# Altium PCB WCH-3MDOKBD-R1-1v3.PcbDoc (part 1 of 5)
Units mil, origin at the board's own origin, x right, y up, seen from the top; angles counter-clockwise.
Board outline 11710.74 x 4477.49 mil, 2 copper layers (Top Layer, Bottom Layer); 422 components, 246 nets, 927 pads, 1295 vias.
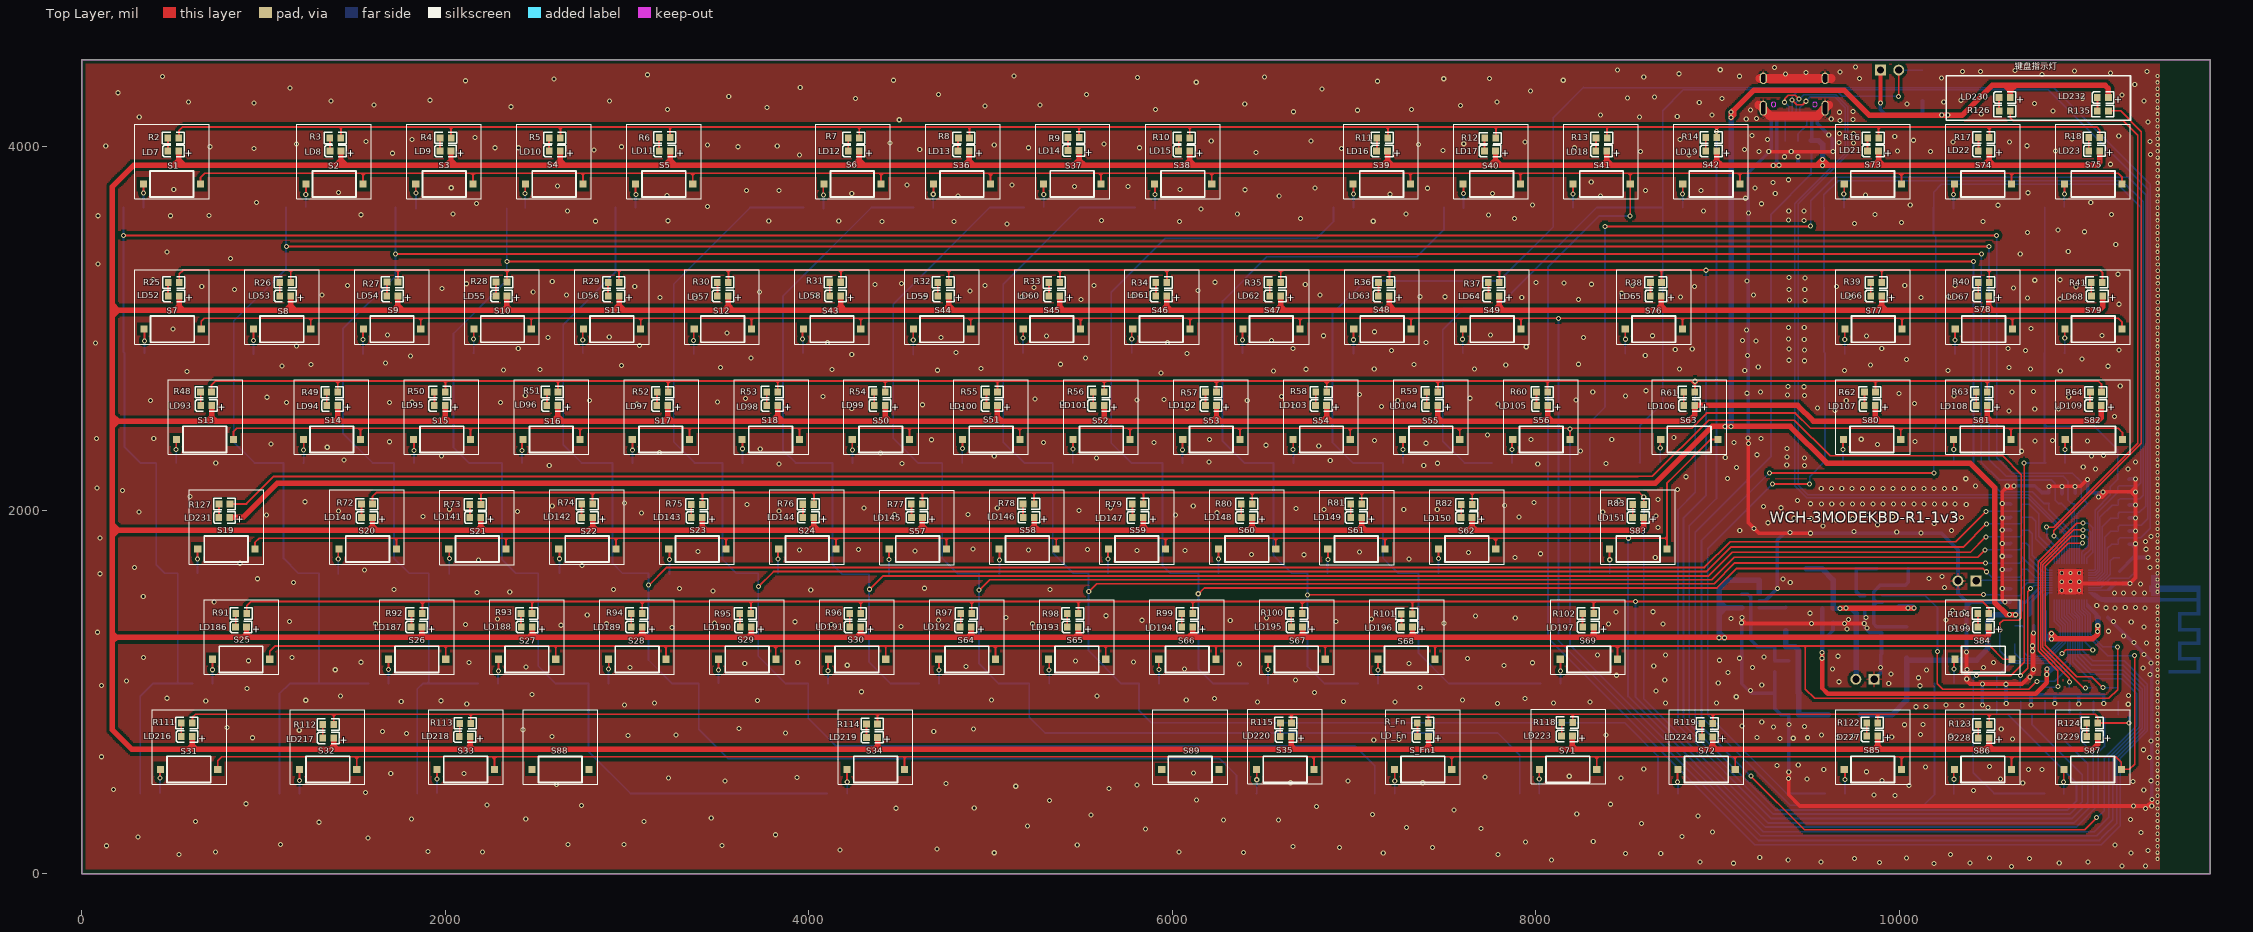
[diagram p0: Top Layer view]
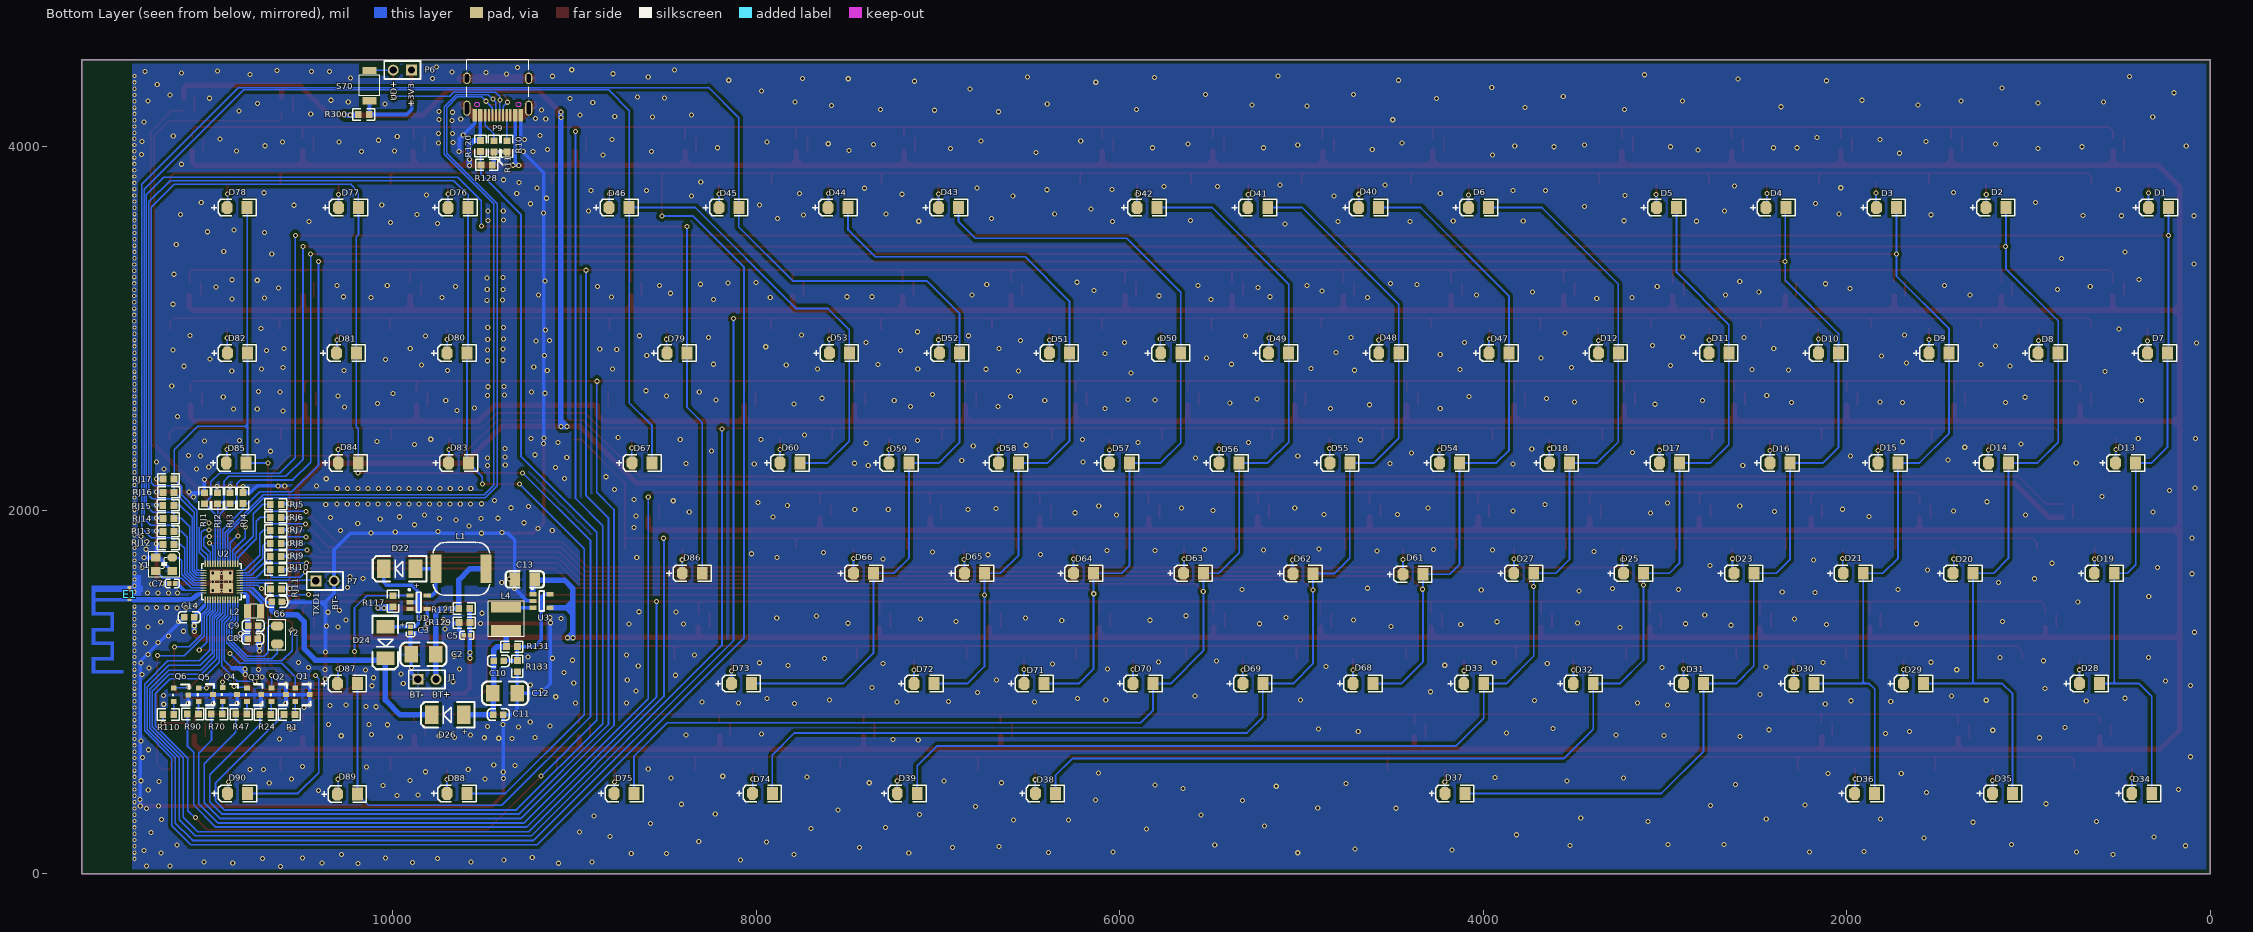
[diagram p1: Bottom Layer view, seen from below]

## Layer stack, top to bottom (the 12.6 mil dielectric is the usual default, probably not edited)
Top Solder: solder mask 0.4, Solder Resist, Dk 3.5
Top Layer: signal copper 1.4
Dielectric1: dielectric 12.6, FR-4, Dk 4.8
Bottom Layer: signal copper 1.4
Bottom Solder: solder mask 0.4, Solder Resist, Dk 3.5

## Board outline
0,0 11710.74,0 11710.74,4477.49 0,4477.49

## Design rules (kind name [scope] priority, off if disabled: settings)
Clearance Clearance_2 [InNamedPolygon('GND1')] p1: gap=6 ignorepadtopadclearanceinfootprint=FALSE
Clearance Clearance_1 [InPolygon] p2: gap=15 ignorepadtopadclearanceinfootprint=FALSE
Clearance [All] p3: gap=6 ignorepadtopadclearanceinfootprint=FALSE
ComponentClearance [All] p1 off: gap=10 collisioncheckmode=3 verticalgap=10 showdistances=FALSE
DiffPairsRouting [All] p1: maxlimit=8 minlimit=6 mostfreqgap=7 toplayer_minwidth=7 toplayer_maxwidth=7 toplayer_prefwidth=7 bottomlayer_minwidth=7 bottomlayer_maxwidth=7 bottomlayer_prefwidth=7 maxuncoupledlength=500
MinimumSolderMaskSliver [All] p1 off: minsoldermaskwidth=10
PolygonConnect PolygonConnect_1 [IsVia] p1: connectstyle=Direct reliefconductorwidth=10 reliefentries=4 polygonreliefangle="90 Angle" airgapwidth=10
PolygonConnect [All] p2: connectstyle=Relief reliefconductorwidth=10 reliefentries=4 polygonreliefangle="90 Angle" airgapwidth=10
RoutingVias [All] p1: holewidth=16 width=28 viastyle="Through Hole" minholewidth=12 minwidth=24 maxholewidth=20 maxwidth=32
SilkToSilkClearance [All] p1 off: silktosilkclearance=10
SilkToSolderMaskClearance SilkscreenOverComponentPads [IsPad] p1 off: minsilkscreentomaskgap=10 clearancetoexposedcopper=TRUE
SolderMaskExpansion [All] p1: expansion=4
Width [All] p1: maxlimit=50 minlimit=6 preferedwidth=10
25 further rules are at their usual default settings.

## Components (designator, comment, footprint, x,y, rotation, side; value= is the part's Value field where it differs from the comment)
C2 "47uF" 3528_C 9898.17,1206.15 r0 bottom
C3 "2.2uF" 0402_C 9901.41,1325.11 r0 bottom
C5 "0.1uF" 0402_C 9607.68,1311.74 r90 bottom
C6 "2.2uF" 0603_C 10610.12,1495.6 r0 bottom
C7 "2.2uF" 0402_C 11228.28,1596.06 r90 bottom
C8 "2.2uF" 0603_C 10741.11,1292.32 r0 bottom
C9 "2.2uF" 0603_C 10739.29,1363.92 r0 bottom
C10 "20pF" 0603_C 9444.56,1170.04 r180 bottom
C11 "0.1uF" 0603_C 9445.37,874.69 r180 bottom
C12 "33uF" 3528_C 9448.23,991.82 r0 bottom
C13 "10uF" 3216_C 9217.66,1618 r180 bottom
C14 "0.1uF" 0603_C 11145.05,1410.61 r180 bottom
D1 "DIODE" 3216+ 340.22,3664.02 r0 bottom locked
D2 "DIODE" 3216+ 1235.34,3664.02 r0 bottom locked
D3 "DIODE" 3216+ 1837.53,3664.02 r0 bottom locked
D4 "DIODE" 3216+ 2444.25,3664.02 r0 bottom locked
D5 "DIODE" 3216+ 3046.47,3664.15 r0 bottom locked
D6 "DIODE" 3216+ 4080.6,3664.02 r0 bottom locked
D7 "DIODE" 3216+ 346.44,2863.47 r0 bottom locked
D8 "DIODE" 3216+ 947.44,2863.47 r0 bottom locked
D9 "DIODE" 3216+ 1547.66,2863.47 r0 bottom locked
D10 "DIODE" 3216+ 2156.27,2863.47 r0 bottom locked
D11 "DIODE" 3216+ 2759.36,2863.47 r0 bottom locked
D12 "DIODE" 3216+ 3367.08,2863.47 r0 bottom locked
D13 "DIODE" 3216+ 521.11,2259.16 r0 bottom locked
D14 "DIODE" 3216+ 1221.16,2259.16 r0 bottom locked
D15 "DIODE" 3216+ 1828.18,2259.16 r0 bottom locked
D16 "DIODE" 3216+ 2422.37,2259.16 r0 bottom locked
D17 "DIODE" 3216+ 3030.91,2259.16 r0 bottom locked
D18 "DIODE" 3216+ 3636.27,2259.16 r0 bottom locked
D19 "DIODE" 3216+ 638.99,1651.91 r0 bottom locked
D20 "DIODE" 3216+ 1416.18,1651.91 r0 bottom locked
D21 "DIODE" 3216+ 2019.59,1651.91 r0 bottom locked
D22 "1N5817" 7227+ 10049.12,1677.06 r180 bottom locked
D23 "DIODE" 3216+ 2621.87,1651.91 r0 bottom locked
D24 "1N5817" 7227+ 10039.49,1183.69 r90 bottom
D25 "DIODE" 3216+ 3228.56,1651.91 r0 bottom locked
D26 "1N5817" 7227+ 9784.18,873.84 r180 bottom
D27 "DIODE" 3216+ 3832.2,1651.91 r0 bottom locked
D28 "DIODE" 3216+ 720.9,1045.22 r0 bottom locked
D29 "DIODE" 3216+ 1688.84,1045.22 r0 bottom locked
D30 "DIODE" 3216+ 2290.6,1045.22 r0 bottom locked
D31 "DIODE" 3216+ 2898.24,1045.22 r0 bottom locked
D32 "DIODE" 3216+ 3505.27,1045.22 r0 bottom locked
D33 "DIODE" 3216+ 4107.43,1045.22 r0 bottom locked
D34 "DIODE" 3216+ 432.75,440.87 r0 bottom locked
D35 "DIODE" 3216+ 1198.31,440.87 r0 bottom locked
D36 "DIODE" 3216+ 1957.05,440.87 r0 bottom locked
D37 "DIODE" 3216+ 4211.36,440.87 r0 bottom locked
D38 "DIODE" 3216+ 6464.02,440.87 r0 bottom locked
D39 "DIODE" 3216+ 7223.58,440.87 r0 bottom locked
D40 "DIODE" 3216+ 4686.32,3664.02 r0 bottom locked
D41 "DIODE" 3216+ 5295.81,3664.02 r0 bottom locked
D42 "DIODE" 3216+ 5905.07,3664.02 r0 bottom locked
D43 "DIODE" 3216+ 6995.94,3664.02 r0 bottom locked
D44 "DIODE" 3216+ 7604.2,3664.02 r0 bottom locked
D45 "DIODE" 3216+ 8205.22,3664.02 r0 bottom locked
D46 "DIODE" 3216+ 8808.27,3664.02 r0 bottom locked
D47 "DIODE" 3216+ 3968.09,2863.47 r0 bottom locked
D48 "DIODE" 3216+ 4574.85,2863.47 r0 bottom locked
D49 "DIODE" 3216+ 5180.47,2863.47 r0 bottom locked
D50 "DIODE" 3216+ 5774.26,2863.47 r0 bottom locked
D51 "DIODE" 3216+ 6386.92,2863.47 r0 bottom locked
D52 "DIODE" 3216+ 6990.5,2863.47 r0 bottom locked
D53 "DIODE" 3216+ 7597.3,2863.47 r0 bottom locked
D54 "DIODE" 3216+ 4239.96,2259.16 r0 bottom locked
D55 "DIODE" 3216+ 4844.14,2259.16 r0 bottom locked
D56 "DIODE" 3216+ 5452.8,2259.16 r0 bottom locked
D57 "DIODE" 3216+ 6055.6,2259.16 r0 bottom locked
D58 "DIODE" 3216+ 6666.44,2259.16 r0 bottom locked
D59 "DIODE" 3216+ 7269.14,2259.16 r0 bottom locked
D60 "DIODE" 3216+ 7869.08,2259.16 r0 bottom locked
D61 "DIODE" 3216+ 4442.3,1646.61 r0 bottom locked
D62 "DIODE" 3216+ 5047.11,1650.08 r0 bottom locked
D63 "DIODE" 3216+ 5649.81,1652.47 r0 bottom locked
D64 "DIODE" 3216+ 6253.38,1652.04 r0 bottom locked
D65 "DIODE" 3216+ 6854.15,1651.91 r0 bottom locked
D66 "DIODE" 3216+ 7463.53,1651.91 r0 bottom locked
D67 "DIODE" 3216+ 8682.18,2259.16 r0 bottom locked
D68 "DIODE" 3216+ 4717.14,1045.22 r0 bottom locked
D69 "DIODE" 3216+ 5322.73,1045.22 r0 bottom locked
D70 "DIODE" 3216+ 5926.55,1045.22 r0 bottom locked
D71 "DIODE" 3216+ 6525.65,1045.22 r0 bottom locked
D72 "DIODE" 3216+ 7131.13,1045.22 r0 bottom locked
D73 "DIODE" 3216+ 8136.22,1045.22 r0 bottom locked
D74 "DIODE" 3216+ 8020.91,440.87 r0 bottom locked
D75 "DIODE" 3216+ 8781.21,440.87 r0 bottom locked
D76 "DIODE" 3216+ 9694.83,3664.02 r0 bottom locked
D77 "DIODE" 3216+ 10297.44,3664.02 r0 bottom locked
D78 "DIODE" 3216+ 10909.68,3664.02 r0 bottom locked
D79 "DIODE" 3216+ 8490.15,2863.47 r0 bottom locked
D80 "DIODE" 3216+ 9700.43,2863.47 r0 bottom locked
D81 "DIODE" 3216+ 10309.39,2863.47 r0 bottom locked
D82 "DIODE" 3216+ 10908.74,2863.47 r0 bottom locked
D83 "DIODE" 3216+ 9691.65,2259.16 r0 bottom locked
D84 "DIODE" 3216+ 10298.64,2259.16 r0 bottom locked
D85 "DIODE" 3216+ 10915.09,2259.16 r0 bottom locked
D86 "DIODE" 3216+ 8406.56,1651.91 r0 bottom locked
D87 "DIODE" 3216+ 10303.89,1045.22 r0 bottom locked
D88 "DIODE" 3216+ 9700.87,440.87 r0 bottom locked
D89 "DIODE" 3216+ 10303.66,437.55 r0 bottom locked
D90 "DIODE" 3216+ 10908.26,441.09 r0 bottom locked
D199 "LED" 0603+ 10492.12,1355.98 r180 top locked
D227 "LED" 0603+ 9879.88,757.01 r180 top locked
D228 "LED" 0603+ 10493.21,746.83 r180 top locked
D229 "LED" 0603+ 11090.96,754.67 r180 top locked
E1 "ANTENNA" ANT-F-1-2.4G-1.6 11446.6,1507.96 r90 bottom
J1 "电源" SIP2-2.54mm 9860.69,1069.05 r270 bottom
L1 "22uH" SMD_7.3x7.8mm 9486.01,1676.23 r270 bottom locked
L2 "22uH" SMD_2x2mm 10762.03,1443.33 r0 bottom
L4 "3.3uH" SMD_5x5mm 9374.78,1464.57 r270 bottom
LD7 "LED" 0603+ 535.31,3974.68 r180 top locked
LD8 "LED" 0603+ 1427.03,3974.68 r180 top locked
LD9 "LED" 0603+ 2032.19,3974.68 r180 top locked
LD10 "LED" 0603+ 2632.59,3974.68 r180 top locked
LD11 "LED" 0603+ 3237.89,3974.68 r180 top locked
LD12 "LED" 0603+ 4277.28,3974.68 r180 top locked
LD13 "LED" 0603+ 4882.15,3974.68 r180 top locked
LD14 "LED" 0603+ 5487.13,3977.21 r180 top locked
LD15 "LED" 0603+ 6095.17,3974.68 r180 top locked
LD16 "LED" 0603+ 7184.25,3974.68 r180 top locked
LD17 "LED" 0603+ 7778.06,3974.68 r180 top locked
LD18 "LED" 0603+ 8390.67,3974.68 r180 top locked
LD19 "LED" 0603+ 8994.91,3974.68 r180 top locked
LD21 "LED" 0603+ 9885.21,3974.68 r180 top locked
LD22 "LED" 0603+ 10493.96,3975.24 r180 top locked
LD23 "LED" 0603+ 11102.17,3976.13 r180 top locked
LD52 "LED" 0603+ 536.96,3178.04 r180 top locked
LD53 "LED" 0603+ 1149.98,3178.04 r180 top locked
LD54 "LED" 0603+ 1740.36,3178.04 r180 top locked
LD55 "LED" 0603+ 2340.06,3178.04 r180 top locked
LD56 "LED" 0603+ 2957.21,3178.04 r180 top locked
LD57 "LED" 0603+ 3558.21,3178.04 r180 top locked
LD58 "LED" 0603+ 4176.71,3178.04 r180 top locked
LD59 "LED" 0603+ 4770.9,3178.04 r180 top locked
LD60 "LED" 0603+ 5381.34,3178.04 r180 top locked
LD61 "LED" 0603+ 5969.32,3178.04 r180 top locked
LD62 "LED" 0603+ 6596.2,3178.04 r180 top locked
LD63 "LED" 0603+ 7194.09,3178.04 r180 top locked
LD64 "LED" 0603+ 7798.02,3178.04 r180 top locked
LD65 "LED" 0603+ 8689.72,3178.04 r180 top locked
LD66 "LED" 0603+ 9902.59,3178.04 r180 top locked
LD67 "LED" 0603+ 10492.22,3178.04 r180 top locked
LD68 "LED" 0603+ 11117.51,3178.04 r180 top locked
LD93 "LED" 0603+ 715.77,2575.56 r180 top locked
LD94 "LED" 0603+ 1409.4,2575.56 r180 top locked
LD95 "LED" 0603+ 2000.22,2575.56 r180 top locked
LD96 "LED" 0603+ 2619.91,2575.56 r180 top locked
LD97 "LED" 0603+ 3225.26,2575.56 r180 top locked
LD98 "LED" 0603+ 3829.13,2575.56 r180 top locked
LD99 "LED" 0603+ 4421.3,2575.56 r180 top locked
LD100 "LED" 0603+ 5038.34,2575.56 r180 top locked
LD101 "LED" 0603+ 5625.34,2575.56 r180 top locked
LD102 "LED" 0603+ 6243.24,2575.56 r180 top locked
LD103 "LED" 0603+ 6848.51,2575.56 r180 top locked
LD104 "LED" 0603+ 7460.26,2575.56 r180 top locked
LD105 "LED" 0603+ 8065.67,2575.56 r180 top locked
LD106 "LED" 0603+ 8874.55,2575.56 r180 top locked
LD107 "LED" 0603+ 9867.1,2575.56 r180 top locked
LD108 "LED" 0603+ 10482.92,2575.56 r180 top locked
LD109 "LED" 0603+ 11109.71,2575.56 r180 top locked
LD140 "LED" 0603+ 1600.46,1958.93 r180 top locked
LD141 "LED" 0603+ 2196.21,1958.93 r180 top locked
LD142 "LED" 0603+ 2812.52,1958.93 r180 top locked
LD143 "LED" 0603+ 3415,1958.93 r180 top locked
LD144 "LED" 0603+ 4028.25,1960.07 r180 top locked
LD145 "LED" 0603+ 4625.6,1959.98 r180 top locked
LD146 "LED" 0603+ 5240.62,1960.08 r180 top locked
LD147 "LED" 0603+ 5840.25,1958.93 r180 top locked
LD148 "LED" 0603+ 6439,1958.93 r180 top locked
LD149 "LED" 0603+ 7041.77,1958.93 r180 top locked
LD150 "LED" 0603+ 7648.87,1958.93 r180 top locked
LD151 "LED" 0603+ 8592.3,1958.93 r180 top locked
LD186 "LED" 0603+ 907.17,1355.98 r180 top locked
LD187 "LED" 0603+ 1872.66,1355.98 r180 top locked
LD188 "LED" 0603+ 2479.54,1355.98 r180 top locked
LD189 "LED" 0603+ 3083.53,1355.98 r180 top locked
LD190 "LED" 0603+ 3683.34,1355.98 r180 top locked
LD191 "LED" 0603+ 4285.49,1355.98 r180 top locked
LD192 "LED" 0603+ 4893.21,1355.98 r180 top locked
LD193 "LED" 0603+ 5483.57,1355.98 r180 top locked
LD194 "LED" 0603+ 6112.64,1355.98 r180 top locked
LD195 "LED" 0603+ 6716.61,1355.98 r180 top locked
LD196 "LED" 0603+ 7321.33,1355.98 r180 top locked
LD197 "LED" 0603+ 8317.72,1355.98 r180 top locked
LD216 "LED" 0603+ 609.65,754.02 r180 top locked
LD217 "LED" 0603+ 1386.96,745.9 r180 top locked
LD218 "LED" 0603+ 2137.51,752.89 r180 top locked
LD219 "LED" 0603+ 4378.55,749.84 r180 top locked
LD220 "LED" 0603+ 6654.88,754.78 r180 top locked
LD223 "LED" 0603+ 8201.34,756.15 r180 top locked
LD224 "LED" 0603+ 8972.68,752.51 r180 top locked
LD230 "LED" 0603+ 10608.7,4268.49 r180 top locked
LD231 "LED" 0603+ 815.15,1959.4 r180 top
LD232 "LED" 0603+ 11149.6,4268.49 r180 top locked
LD_Fn "LED" 0603+ 7409.48,754.78 r180 top locked
P6 "Header 2" SIP2-2.54mm 9896.11,4420.24 r90 bottom
P7 "Header 2" SIP2-2.54mm 10421.86,1610.46 r270 bottom
P9 "TYPE-C" TYPE-C-Receptacle-2.0 9421.22,4172.15 r0 bottom locked
Q1 "MOSFET P" SOT-23 10535.74,1021.55 r270 bottom
Q2 "MOSFET P" SOT-23 10665.45,1021.55 r270 bottom
Q3 "MOSFET P" SOT-23 10801.32,1021.55 r270 bottom
Q4 "MOSFET P" SOT-23 10934.85,1022.44 r270 bottom
Q5 "MOSFET P" SOT-23 11066.81,1021.46 r270 bottom
Q6 "MOSFET P" SOT-23 11203.23,1021.09 r270 bottom
R1 "0R" 0603 10597.59,874.77 r180 bottom
R2 "0R" 0603 474.9,4046.43 r0 top locked
R3 "0R" 0603 1365.64,4047.02 r0 top locked
R4 "0R" 0603 1972.09,4047.85 r0 top locked
R5 "0R" 0603 2573.31,4046.3 r0 top locked
R6 "0R" 0603 3176.94,4049.03 r0 top locked
R7 "0R" 0603 4217.68,4046.45 r0 top locked
R8 "0R" 0603 4823.58,4045.73 r0 top locked
R9 "0R" 0603 5426.68,4049.16 r0 top locked
R10 "NC(5.1K)" 0603 9370.04,4031.44 r270 bottom
R10 "0R" 0603 6035.26,4046.93 r0 top locked
R11 "NC(5.1K)" 0603 9442.13,4032.34 r270 bottom
R11 "0R" 0603 7125.5,4047.46 r0 top locked
R12 "0R" 0603 7719.46,4045.31 r0 top locked
R13 "0R" 0603 8331.16,4046.03 r0 top locked
R14 "0R" 0603 8934.65,4049.64 r0 top locked
R16 "0R" 0603 9824.78,4046.75 r0 top locked
R17 "0R" 0603 10434.11,4048.46 r0 top locked
R18 "0R" 0603 11041.59,4048.25 r0 top locked
R24 "0R" 0603 10730.76,874.77 r180 bottom
R25 "0R" 0603 476.53,3251.67 r0 top locked
R26 "0R" 0603 1090.21,3252.61 r0 top locked
R27 "0R" 0603 1679.96,3253.07 r0 top locked
R28 "0R" 0603 2279.96,3253.12 r0 top locked
R29 "0R" 0603 2896.29,3252.16 r0 top locked
R30 "0R" 0603 3497.56,3252.9 r0 top locked
R31 "0R" 0603 4116.17,3253.05 r0 top locked
R32 "0R" 0603 4709.97,3252.74 r0 top locked
R33 "0R" 0603 5321.22,3252.04 r0 top locked
R34 "0R" 0603 5909.54,3252.33 r0 top locked
R35 "0R" 0603 6535.68,3252.61 r0 top locked
R36 "0R" 0603 7134.17,3252.61 r0 top locked
R37 "0R" 0603 7738.63,3252.61 r0 top locked
R38 "0R" 0603 8630.24,3252.61 r0 top locked
R39 "0R" 0603 9842,3252.32 r0 top locked
R40 "0R" 0603 10433.26,3252.61 r0 top locked
R41 "0R" 0603 11055.61,3252.61 r0 top locked
R47 "0R" 0603 10863.53,876.76 r180 bottom
R48 "0R" 0603 654.54,2648.31 r0 top locked
R49 "0R" 0603 1348.76,2648.31 r0 top locked
R50 "0R" 0603 1940.9,2649.63 r0 top locked
R51 "0R" 0603 2560.01,2649.18 r0 top locked
R52 "0R" 0603 3166.04,2648.1 r0 top locked
R53 "0R" 0603 3768.87,2648.8 r0 top locked
R54 "0R" 0603 4360.67,2648.31 r0 top locked
R55 "0R" 0603 4978.02,2648.54 r0 top locked
R56 "0R" 0603 5564.94,2648.53 r0 top locked
R57 "0R" 0603 6182.61,2648.31 r0 top locked
R58 "0R" 0603 6788.76,2648.31 r0 top locked
R59 "0R" 0603 7400.14,2648.31 r0 top locked
R60 "0R" 0603 8003.81,2648.31 r0 top locked
R61 "0R" 0603 8814.07,2649.19 r0 top locked
R62 "0R" 0603 9807.62,2648.31 r0 top locked
R63 "0R" 0603 10422.52,2648.31 r0 top locked
R64 "0R" 0603 11050.61,2648.43 r0 top locked
R70 "0R" 0603 10997.37,877.22 r180 bottom
R72 "0R" 0603 1539.53,2031.99 r0 top locked
R73 "0R" 0603 2136.29,2030.9 r0 top locked
R74 "0R" 0603 2750.71,2032.03 r0 top locked
R75 "0R" 0603 3354.25,2031.41 r0 top locked
R76 "0R" 0603 3967.83,2031.83 r0 top locked
R77 "0R" 0603 4564.59,2033.84 r0 top locked
R78 "0R" 0603 5179.18,2034.04 r0 top locked
R79 "0R" 0603 5780.5,2032.89 r0 top locked
R80 "0R" 0603 6379.58,2032.89 r0 top locked
R81 "0R" 0603 6981.64,2032.88 r0 top locked
R82 "0R" 0603 7589.34,2029.77 r0 top locked
R83 "0R" 0603 8532.99,2031.46 r0 top locked
R90 "0R" 0603 11128.49,877.43 r180 bottom
R91 "0R" 0603 847.94,1430.13 r0 top locked
R92 "0R" 0603 1814.29,1430.13 r0 top locked
R93 "0R" 0603 2417.39,1430.13 r0 top locked
R94 "0R" 0603 3023.78,1430.13 r0 top locked
R95 "0R" 0603 3621.34,1430.13 r0 top locked
R96 "0R" 0603 4225.6,1430.13 r0 top locked
R97 "0R" 0603 4836.65,1430.13 r0 top locked
R98 "0R" 0603 5422.61,1430.13 r0 top locked
R99 "0R" 0603 6052.01,1430.13 r0 top locked
R100 "0R" 0603 6654.64,1430.5 r0 top locked
R101 "0R" 0603 7260.23,1428.03 r0 top locked
R102 "0R" 0603 8257.08,1430.13 r0 top locked
R104 "0R" 0603 10431.48,1430.13 r0 top locked
R110 "0R" 0603 11263.47,875.52 r180 bottom
R111 "0R" 0603 548.72,828.35 r0 top locked
R112 "0R" 0603 1326.33,820.21 r0 top locked
R113 "0R" 0603 2080.1,826.72 r0 top locked
R114 "0R" 0603 4317.94,822.75 r0 top locked
R115 "0R" 0603 6594.87,828.74 r0 top locked
R117 "1K" 0603 9997.61,1528.94 r270 bottom
R118 "0R" 0603 8142.55,830.64 r0 top locked
R119 "0R" 0603 8913.06,826.13 r0 top locked
R120 "10K" 0603 9515.84,3972.2 r90 bottom
R121 "1M" 0603 9574.94,1458.22 r0 bottom
R122 "0R" 0603 9820.51,829.67 r0 top locked
R123 "0R" 0603 10433.47,821.07 r0 top locked
R124 "0R" 0603 11030.68,827.9 r0 top locked
R126 "1K" 0603 10548.37,4195.24 r0 top locked
R127 "1K" 0603 755.91,2033.74 r0 top
R128 "10K" 0603 9452.55,3898.85 r0 bottom
R129 "1M" 0603 9634.85,1380.06 r180 bottom
R131 "47K" 0603 9373.45,1248.39 r180 bottom
R133 "10K" 0603 9313.87,1111.26 r90 bottom
R135 "1K" 0603 11089.03,4195.24 r0 top locked
R300 "10K" 0603 10128.51,4175.66 r0 bottom
R_Fn "0R" 0603 7348.18,828.57 r0 top
RJ1 "10K" 0603 11034.95,2095.15 r270 bottom
RJ2 "10K" 0603 10963.33,2095.38 r270 bottom
RJ3 "10K" 0603 10893.01,2095.98 r270 bottom
RJ4 "10K" 0603 10822.08,2096.17 r270 bottom
RJ5 "10K" 0603 10611.9,2031.32 r0 bottom
RJ6 "10K" 0603 10611.9,1959.77 r0 bottom
RJ7 "10K" 0603 10611.9,1888.22 r0 bottom
RJ8 "10K" 0603 10611.9,1816.66 r0 bottom
RJ9 "10K" 0603 10611.9,1745.11 r0 bottom
RJ10 "10K" 0603 10611.9,1673.55 r0 bottom
RJ11 "10K" 0603 10610.94,1566.03 r0 bottom
RJ12 "10K" 0603 11263.19,1811.41 r180 bottom
RJ13 "10K" 0603 11263.19,1882.98 r180 bottom
RJ14 "10K" 0603 11263.19,1954.56 r180 bottom
RJ15 "10K" 0603 11263.22,2026.18 r180 bottom
RJ16 "10K" 0603 11262.57,2097.64 r180 bottom
RJ17 "10K" 0603 11262.9,2169.74 r180 bottom
S1 "SW-PB" SMD_6.1x3.65x2.5mm-KEY 654.86,3793.8 r180 top locked
S2 "SW-PB" SMD_6.1x3.65x2.5mm-KEY 1548.73,3793.8 r180 top locked
S3 "SW-PB" SMD_6.1x3.65x2.5mm-KEY 2153.27,3793.8 r180 top locked
S4 "SW-PB" SMD_6.1x3.65x2.5mm-KEY 2757.8,3793.8 r180 top locked
S5 "SW-PB" SMD_6.1x3.65x2.5mm-KEY 3362.34,3793.8 r180 top locked
S6 "SW-PB" SMD_6.1x3.65x2.5mm-KEY 4398.26,3793.97 r180 top locked
S7 "SW-PB" SMD_6.1x3.65x2.5mm-KEY 658.49,2994.96 r180 top locked
S8 "SW-PB" SMD_6.1x3.65x2.5mm-KEY 1260.41,2994.96 r180 top locked
S9 "SW-PB" SMD_6.1x3.65x2.5mm-KEY 1866.19,2994.96 r180 top locked
S10 "SW-PB" SMD_6.1x3.65x2.5mm-KEY 2473.99,2994.96 r180 top locked
S11 "SW-PB" SMD_6.1x3.65x2.5mm-KEY 3075.53,2994.96 r180 top locked
S12 "SW-PB" SMD_6.1x3.65x2.5mm-KEY 3685.01,2994.96 r180 top locked
S13 "SW-PB" SMD_6.1x3.65x2.5mm-KEY 836.42,2388.74 r180 top locked
S14 "SW-PB" SMD_6.1x3.65x2.5mm-KEY 1535.07,2388.74 r180 top locked
S15 "SW-PB" SMD_6.1x3.65x2.5mm-KEY 2140.31,2388.74 r180 top locked
S16 "SW-PB" SMD_6.1x3.65x2.5mm-KEY 2742.63,2388.74 r180 top locked
S17 "SW-PB" SMD_6.1x3.65x2.5mm-KEY 3344.57,2388.74 r180 top locked
S18 "SW-PB" SMD_6.1x3.65x2.5mm-KEY 3948.78,2388.74 r180 top locked
S19 "SW-PB" SMD_6.1x3.65x2.5mm-KEY 953.93,1785.35 r180 top locked
S20 "SW-PB" SMD_6.1x3.65x2.5mm-KEY 1731.56,1785.35 r180 top locked
S21 "SW-PB" SMD_6.1x3.65x2.5mm-KEY 2335.05,1785.35 r180 top locked
S22 "SW-PB" SMD_6.1x3.65x2.5mm-KEY 2939.64,1785.35 r180 top locked
S23 "SW-PB" SMD_6.1x3.65x2.5mm-KEY 3545.39,1785.35 r180 top locked
S24 "SW-PB" SMD_6.1x3.65x2.5mm-KEY 4150.01,1785.35 r180 top locked
S25 "SW-PB" SMD_6.1x3.65x2.5mm-KEY 1035.51,1178.83 r180 top locked
S26 "SW-PB" SMD_6.1x3.65x2.5mm-KEY 2003.11,1178.83 r180 top locked
S27 "SW-PB" SMD_6.1x3.65x2.5mm-KEY 2608.46,1178.83 r180 top locked
S28 "SW-PB" SMD_6.1x3.65x2.5mm-KEY 3214.49,1178.83 r180 top locked
S29 "SW-PB" SMD_6.1x3.65x2.5mm-KEY 3819.1,1178.83 r180 top locked
S30 "SW-PB" SMD_6.1x3.65x2.5mm-KEY 4423.72,1178.83 r180 top locked
S31 "SW-PB" SMD_6.1x3.65x2.5mm-KEY 748.99,573.38 r180 top locked
S32 "SW-PB" SMD_6.1x3.65x2.5mm-KEY 1513.74,573.38 r180 top locked
S33 "SW-PB" SMD_6.1x3.65x2.5mm-KEY 2271.01,573.38 r180 top
S34 "SW-PB" SMD_6.1x3.65x2.5mm-KEY 4526,573.38 r180 top locked
S35 "SW-PB" SMD_6.1x3.65x2.5mm-KEY 6778.66,573.38 r180 top locked
S36 "SW-PB" SMD_6.1x3.65x2.5mm-KEY 5000.82,3793.97 r180 top locked
S37 "SW-PB" SMD_6.1x3.65x2.5mm-KEY 5607.27,3794.25 r180 top locked
S38 "SW-PB" SMD_6.1x3.65x2.5mm-KEY 6216.74,3794.24 r180 top locked
S39 "SW-PB" SMD_6.1x3.65x2.5mm-KEY 7309.83,3793.8 r180 top locked
S40 "SW-PB" SMD_6.1x3.65x2.5mm-KEY 7914.98,3793.8 r180 top locked
S41 "SW-PB" SMD_6.1x3.65x2.5mm-KEY 8519.58,3793.88 r180 top locked
S42 "SW-PB" SMD_6.1x3.65x2.5mm-KEY 9122.54,3793.8 r180 top locked
S43 "SW-PB" SMD_6.1x3.65x2.5mm-KEY 4286.55,2994.96 r180 top locked
S44 "SW-PB" SMD_6.1x3.65x2.5mm-KEY 4890.96,2994.96 r180 top locked
S45 "SW-PB" SMD_6.1x3.65x2.5mm-KEY 5495.41,2994.96 r180 top locked
S46 "SW-PB" SMD_6.1x3.65x2.5mm-KEY 6097.77,2994.96 r180 top locked
S47 "SW-PB" SMD_6.1x3.65x2.5mm-KEY 6703.15,2994.96 r180 top locked
S48 "SW-PB" SMD_6.1x3.65x2.5mm-KEY 7312.97,2994.96 r180 top locked
S49 "SW-PB" SMD_6.1x3.65x2.5mm-KEY 7917.42,2994.96 r180 top locked
S50 "SW-PB" SMD_6.1x3.65x2.5mm-KEY 4554.49,2388.74 r180 top locked
S51 "SW-PB" SMD_6.1x3.65x2.5mm-KEY 5161.33,2388.74 r180 top locked
S52 "SW-PB" SMD_6.1x3.65x2.5mm-KEY 5768.19,2388.74 r180 top locked
S53 "SW-PB" SMD_6.1x3.65x2.5mm-KEY 6372.38,2388.74 r180 top locked
S54 "SW-PB" SMD_6.1x3.65x2.5mm-KEY 6979.24,2388.74 r180 top locked
S55 "SW-PB" SMD_6.1x3.65x2.5mm-KEY 7581.17,2388.74 r180 top locked
S56 "SW-PB" SMD_6.1x3.65x2.5mm-KEY 8188.01,2388.74 r180 top locked
S57 "SW-PB" SMD_6.1x3.65x2.5mm-KEY 4757.72,1785.35 r180 top locked
S58 "SW-PB" SMD_6.1x3.65x2.5mm-KEY 5361.23,1785.35 r180 top locked
S59 "SW-PB" SMD_6.1x3.65x2.5mm-KEY 5963.21,1785.35 r180 top locked
S60 "SW-PB" SMD_6.1x3.65x2.5mm-KEY 6568.85,1785.35 r180 top locked
S61 "SW-PB" SMD_6.1x3.65x2.5mm-KEY 7170.54,1785.35 r180 top locked
S62 "SW-PB" SMD_6.1x3.65x2.5mm-KEY 7778.96,1785.35 r180 top locked
S63 "SW-PB" SMD_6.1x3.65x2.5mm-KEY 9001.52,2388.74 r180 top locked
S64 "SW-PB" SMD_6.1x3.65x2.5mm-KEY 5028.29,1178.83 r180 top locked
S65 "SW-PB" SMD_6.1x3.65x2.5mm-KEY 5634.21,1178.83 r180 top locked
S66 "SW-PB" SMD_6.1x3.65x2.5mm-KEY 6240.4,1178.83 r180 top locked
S67 "SW-PB" SMD_6.1x3.65x2.5mm-KEY 6841.4,1178.83 r180 top locked
S68 "SW-PB" SMD_6.1x3.65x2.5mm-KEY 7445.87,1178.83 r180 top locked
S69 "SW-PB" SMD_6.1x3.65x2.5mm-KEY 8449.06,1178.83 r180 top locked
S70 "Download" 贴片按键 10127.09,4251.02 r90 bottom
S71 "SW-PB" SMD_6.1x3.65x2.5mm-KEY 8335.08,573.38 r180 top locked
S72 "SW-PB" SMD_6.1x3.65x2.5mm-KEY 9096.51,573.38 r180 top locked
S73 "SW-PB" SMD_6.1x3.65x2.5mm-KEY 10011.03,3793.8 r180 top locked
S74 "SW-PB" SMD_6.1x3.65x2.5mm-KEY 10617.3,3793.8 r180 top locked
S75 "SW-PB" SMD_6.1x3.65x2.5mm-KEY 11223.57,3793.8 r180 top locked
S76 "SW-PB" SMD_6.1x3.65x2.5mm-KEY 8806.65,2994.96 r180 top locked
S77 "SW-PB" SMD_6.1x3.65x2.5mm-KEY 10014.84,2994.96 r180 top locked
S78 "SW-PB" SMD_6.1x3.65x2.5mm-KEY 10621.68,2994.96 r180 top locked
S79 "SW-PB" SMD_6.1x3.65x2.5mm-KEY 11224.93,2994.96 r180 top locked
S80 "SW-PB" SMD_6.1x3.65x2.5mm-KEY 10007.05,2388.74 r180 top locked
S81 "SW-PB" SMD_6.1x3.65x2.5mm-KEY 10612.8,2388.74 r180 top locked
S82 "SW-PB" SMD_6.1x3.65x2.5mm-KEY 11226.87,2388.74 r180 top locked
S83 "SW-PB" SMD_6.1x3.65x2.5mm-KEY 8720.81,1785.35 r180 top locked
S84 "SW-PB" SMD_6.1x3.65x2.5mm-KEY 10620.02,1178.83 r180 top locked
S85 "SW-PB" SMD_6.1x3.65x2.5mm-KEY 10011.76,573.38 r180 top locked
S86 "SW-PB" SMD_6.1x3.65x2.5mm-KEY 10617.3,573.38 r180 top locked
S87 "SW-PB" SMD_6.1x3.65x2.5mm-KEY 11220.65,573.38 r180 top locked
S88 "SW-PB" SMD_6.1x3.65x2.5mm-KEY 2791.88,573.08 r180 top (schematic designator S33)
S89 "SW-PB" SMD_6.1x3.65x2.5mm-KEY 6256.7,572.46 r180 top (schematic designator S33)
S_Fn1 "SW-PB" SMD_6.1x3.65x2.5mm-KEY 7536.95,573.38 r180 top locked
U1 "CE8301C33M" SOT-23-5 9904.01,1530.18 r270 bottom
U2 "CH582M" QFN48_5X5 10940.73,1605.7 r90 bottom locked
U3 "CE8502AM" SOT-23-5 9228.25,1537.45 r270 bottom
Y1 "32M" XT3225 11211.35,1738.56 r0 bottom
Y2 "32.768K" FC-135 10634.75,1263.98 r90 bottom

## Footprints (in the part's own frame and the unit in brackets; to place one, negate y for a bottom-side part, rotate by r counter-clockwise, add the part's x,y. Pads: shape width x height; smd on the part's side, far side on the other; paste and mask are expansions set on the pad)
0402_C [mm]
  rect 0.65x0.6 smd mask+0.051: 1(0,0) 2(0,-0.85)
  silkscreen extent -0.58,-1.4 0.57,0.55
0603 [mm]
  rect 0.93x0.98 smd: 1(0,0) 2(1.54,0)
  silkscreen extent -0.76,-0.79 2.3,0.79
0603+ [mm]
  rect 0.93x0.98 smd: A(0,0) K(1.54,0)
  silkscreen extent -0.76,-0.79 2.27,0.79
0603_C [mil]
  rect 36x36 smd: 1(0,0) 2(55,0)
  silkscreen extent -33,-31 88,31
3216+ [mil]
  oct 60x70 smd: 1(0,0)
  rect 60x70 smd: 2(-110,0)
  silkscreen extent -160,-45 87,45
3216_C [mil]
  rect 60x70 smd: 1(0,0) 2(-110,0)
  silkscreen extent -160,-45 50,45
3528_C [mil]
  rect 75x90 smd: 1(0,0) 2(-135,0)
  silkscreen extent -195,-65 60,65
7227+ [mil]
  rect 75x100 smd: 1(175,0) 2(0,0)
  silkscreen extent -60,-70 235,70
ANT-F-1-2.4G-1.6 [mm]
  rect 0.8x0.6 smd mask+0: 0(1.483,0)
  rect 0.4x0.6 smd mask+0: 1(0,0)
  Top Layer region: 0.24,-0.304 -0.26,-0.304 -0.26,5.027 0.24,5.027
  Top Layer region: 1.94,-0.304 1.04,-0.304 1.04,5.002 1.94,5.002
  Top Layer region: 1.94,4.796 -2.26,4.796 -2.26,5.296 1.94,5.296
  Top Layer region: -1.76,2.157 -2.26,2.157 -2.26,4.977 -1.76,4.977
  Top Layer region: -1.85,2.156 -4.39,2.156 -4.39,2.651 -1.85,2.651
  Top Layer region: -3.96,2.156 -4.46,2.156 -4.46,4.976 -3.96,4.976
  Top Layer region: -3.96,4.796 -6.36,4.796 -6.36,5.296 -3.96,5.296
  Top Layer region: -5.86,2.157 -6.36,2.157 -6.36,4.977 -5.86,4.977
  Top Layer region: -5.875,2.157 -8.364,2.157 -8.364,2.657 -5.875,2.657
  Top Layer region: -8.06,2.157 -8.56,2.157 -8.56,4.977 -8.06,4.977
  Top Layer region: -8.06,4.796 -10.36,4.796 -10.36,5.296 -8.06,5.296
  Top Layer region: -9.86,0.856 -10.36,0.856 -10.36,4.976 -9.86,4.976
FC-135 [mil]
  oct 50x70 smd: 1(0,0) 2(98.43,0)
  silkscreen extent -35,-47 133,47
QFN48_5X5 [mm]
  round 0.559 hole 0.381 mask+0.102: 0(-1.219,-1.219) 0(-1.219,1.219) 0(0,0) 0(1.219,-1.219) 0(1.219,1.219)
  rect 1.397x1.397 smd mask+0: 0(-0.901,-0.895) 0(-0.901,0.908) 0(0.902,-0.895) 0(0.902,0.908)
  oval 0.18x0.9 smd: 1(-1.575,-2.519) 2(-1.225,-2.519) 3(-0.875,-2.519) 4(-0.525,-2.519) 5(-0.175,-2.519) 6(0.175,-2.519) 7(0.525,-2.519) 8(0.875,-2.519) 9(1.225,-2.519) 10(1.575,-2.519) 25(1.575,2.519) 26(1.225,2.519) 27(0.875,2.519) 28(0.525,2.519) 29(0.175,2.519) 30(-0.175,2.519) 31(-0.525,2.519) 32(-0.875,2.519) 33(-1.225,2.519) 34(-1.575,2.519)
  oval 0.9x0.18 smd: 11(2.514,-2.269) 12(2.514,-1.919) 13(2.514,-1.569) 14(2.514,-1.219) 15(2.514,-0.869) 16(2.514,-0.519) 17(2.514,-0.169) 18(2.514,0.181) 19(2.514,0.531) 20(2.514,0.881) 21(2.514,1.231) 22(2.514,1.581) 23(2.514,1.931) 24(2.514,2.281) 35(-2.514,2.281) 36(-2.514,1.931) 37(-2.514,1.581) 38(-2.514,1.231) 39(-2.514,0.881) 40(-2.514,0.531) 41(-2.514,0.181) 42(-2.514,-0.169) 43(-2.514,-0.519) 44(-2.514,-0.869) 45(-2.514,-1.219) 46(-2.514,-1.569) 47(-2.514,-1.919) 48(-2.514,-2.269)
  silkscreen extent -2.51,-3.31 2.51,2.77
SIP2-2.54mm [mil]
  rect 60x60 hole 40: 1(0,0)
  round 60 hole 40: 2(0,100)
  silkscreen extent -50,-50 50,150
SMD_2x2mm [mm]
  rect 1x2 smd: 1(-0.905,0) 2(0.905,0)
  silkscreen extent -0.47,-1 0.53,1
SMD_5x5mm [mm]
  rect 1.5x4.2 smd: 1(0,0) 2(3.23,0)
  silkscreen extent -0.88,-2.5 4.12,2.5
SMD_6.1x3.65x2.5mm-KEY [mm]
  rect 1x1 smd: 1(0,0) 2(8,0)
  silkscreen extent 0.98,-1.83 7.08,1.83
SMD_7.3x7.8mm [mm]
  rect 4x1.5 smd: 1(0,0) 2(0,-7)
  silkscreen extent -3.69,-7.38 3.69,0.51
SOT-23 [mm]
  rect 0.7x0.8 smd: 1(0,0) 2(1.9,0) 3(0.95,2.02)
  silkscreen extent -0.51,-0.13 2.41,2.16
SOT-23-5 [mm]
  rect 0.6x1 smd: 1(0,0) 2(0.95,0) 3(1.9,0) 4(1.9,2.4) 5(0,2.4)
  silkscreen extent -0.92,-0.23 2.35,1.54
TYPE-C-Receptacle-2.0 [mm]
  oval 1x1.6 hole 0.6 slot 1.2 at 90 deg: 0(-4.32,-5.15) 0(4.32,-5.15)
  oval 1x2.1 hole 0.6 slot 1.7 at 90 deg: 0(-4.32,-0.97) 0(4.32,-0.97)
  rect 0.6x1.75 smd: A1(-3.225,0) A4(-2.45,0) B1(3.225,0) B4(2.45,0)
  rect 0.3x1.75 smd: A5(-1.25,0) A6(-0.25,0) A7(0.25,0) A8(1.25,0) B5(1.75,0) B6(0.75,0) B7(-0.75,0) B8(-1.75,0)
  Keep-Out Layer circle w0.1: c2.89,-1.5 r0.325
  Keep-Out Layer circle w0.1: c-2.89,-1.5 r0.325
  silkscreen extent -4.32,-7.75 4.32,-2.55
XT3225 [mm]
  oct 1.3x1.1 smd: 1(0,0)
  rect 1.3x1.1 smd: 2(2.3,0) 3(2.3,1.9) 4(0,1.9)
  silkscreen extent -1.02,-0.8 3.27,2.74
贴片按键 [mm]
  rect 1x2 smd: 1(0,0) 3(4.242,0)
  silkscreen extent 0.69,-1.45 3.55,1.45

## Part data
C2 C3 C5 C7: library part C0402
C6 C8 C9 C10 C11 C12 C13 C14: library part CAP, "Capacitor"
D1 D2 D3 D4 D5 D6 D7 D8 D9 D10 D11 D12 D13 D14 D15 D16 D17 D18 D19 D20 D21 D23 D25 D27 D28 D29 D30 D31 D32 D33 D34 D35 D36 D37 D38 D39 D40 D41 D42 D43 D44 D45 D46 D47 D48 D49 D50 D51 D52 D53 D54 D55 D56 D57 D58 D59 D60 D61 D62 D63 D64 D65 D66 D67 D68 D69 D70 D71 D72 D73 D74 D75 D76 D77 D78 D79 D80 D81 D82 D83 D84 D85 D86 D87 D88 D89 D90: "Diode"
D22 D24 D26: library part "D Schottky", "Schottky Diode"
E1: "Generic Antenna"
J1: library part HDR1x2, "Connector"
L1: library part 1.05.0226.04, Value2=额?, Value3=˳?
L2: library part INDUCTANCE, "Inductance"
L4: library part INDUCTOR
P6 P7: "Header, 2-Pin"
P9: library part TYPE-C1
R1 R2 R3 R4 R5 R6 R7 R8 R9 R10 R11 R12 R13 R14 R16 R17 R18 R24 R25 R26 R27 R28 R29 R30 R31 R32 R33 R34 R35 R36 R37 R38 R39 R40 R41 R47 R48 R49 R50 R51 R52 R53 R54 R55 R56 R57 R58 R59 R60 R61 R62 R63 R64 R70 R72 R73 R74 R75 R76 R77 R78 R79 R80 R81 R82 R83 R90 R91 R92 R93 R94 R95 R96 R97 R98 R99 R100 R101 R102 R104 R110 R111 R112 R113 R114 R115 R118 R119 R122 R123 R124 R126 R127 R135 R_Fn: library part RES2
R10 R11 RJ1 RJ2 RJ3 RJ4 RJ5 RJ6 RJ7 RJ8 RJ9 RJ10 RJ11 RJ12 RJ13 RJ14 RJ15 RJ16 RJ17: library part Res2, "Resistor"
R117 R120 R121 R128 R129: library part RES, "Resistor"
R131 R133: library part R
R300: library part DZ
S70: library part SW-PB, "Switch"
U1: library part 1.07.0021.05
U2: "RISC-V MCU with BLE/2*USB/ADC/PWM/SPI/I2C/4*UART"
U3: library part FP6160
Y1 Y2: library part XTAL, "Crystal Oscillator"

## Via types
v1: diameter 28, hole 16, Top Layer to Bottom Layer, tented both sides, 1167 vias
v2: diameter 24, hole 12, Top Layer to Bottom Layer, tented both sides, 128 vias

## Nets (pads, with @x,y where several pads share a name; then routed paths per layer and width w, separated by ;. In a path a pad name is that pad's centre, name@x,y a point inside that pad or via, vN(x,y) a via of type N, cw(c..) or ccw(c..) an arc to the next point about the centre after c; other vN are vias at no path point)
+3V3: C6.2 D24.2 D26.2 LD230.A LD231.A LD232.A R300.2 U2.3 | length 17038.3
  Top Layer w30: LD231.A@815.15,1959.4 888.22,1959.4 1075.86,2147.05 8656.27,2147.05 8969.78,2460.55 9398.24,2460.55 9600.59,2258.21 10388.69,2258.21 10523.13,2123.77 10523.13,1491.63 10590.66,1424.1 v1(10638.03,1424.1) v1@10638.73,1424.1 ; 9088.24,4199.51 9073.6,4184.87 v1(9073.6,4158.49) 9088.24,4173.14 9088.24,4197.47 9200.05,4309.28 9695.26,4309.28 9834.04,4170.5 10343.4,4170.5 10509.23,4336.33 ; 10509.5,4336.6 10509.23,4336.33 ; LD230.A@10608.7,4268.49 10608.7,4307.6 ; LD232.A@11149.6,4268.49 11149.6,4318.63 11131.9,4336.33 10637.43,4336.33 ; 10509.23,4336.33 10579.97,4336.33 ; 10579.97,4336.33 10600.28,4336.33 ; 10579.97,4336.33 10608.7,4307.6 ; 10600.28,4336.33 10637.43,4336.33 ; 10600.28,4336.33 10608.7,4327.91 10608.7,4307.6 ; 10608.7,4307.6 10637.43,4336.33
  Bottom Layer w7: U2.3@10841.57,1571.27 10775.72,1571.27 ; C6.2@10673.61,1487.11 C6.2@10682.1,1495.6 ; C6.2@10673.61,1487.11 C6.2@10682.8,1487.11 ; C6.2@10673.61,1487.11 C6.2@10665.12,1495.6 C6.2@10682.1,1495.6 ; C6.2@10682.1,1495.6 10691.29,1495.6 ; C6.2@10682.8,1487.11 10691.56,1487.11 ; C6.2@10682.8,1487.11 10691.29,1495.6 ; 10691.29,1495.6 10700.04,1495.6 ; 10691.29,1495.6 10691.29,1487.37 10691.56,1487.11 ; 10691.29,1495.6 10766.96,1571.27 10775.72,1571.27 ; 10691.56,1487.11 10700.04,1495.6 ; 10700.04,1495.6 10775.72,1571.27
  Bottom Layer w30: v1(9072.52,2458.76) 9042.56,2458.76 v1(9040.87,2460.45) 9072.5,2492.08 9073.6,2492.08 ; v1@9073.6,2460.42 9073.6,2492.08 ; v1@9073.6,4188.5 v1(9073.6,4158.49) 9073.6,2492.08 ; D26.2@9784.18,873.84 9958.9,873.84 10039.49,954.44 D24.2@10039.49,1183.69 10048.53,1174.65 10424.35,1174.65 10486.97,1237.27 10486.97,1386.16 10524.9,1424.1 v1(10638.03,1424.1) ; R300.2@10192.61,4172.19 v1(10265.81,4172.19) ; v1@10638.08,1424.05 10665.12,1451.09 C6.2@10665.12,1495.6
  other v1: 10604.43,1426.07 10232.93,4171.94 9073.24,4188.5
